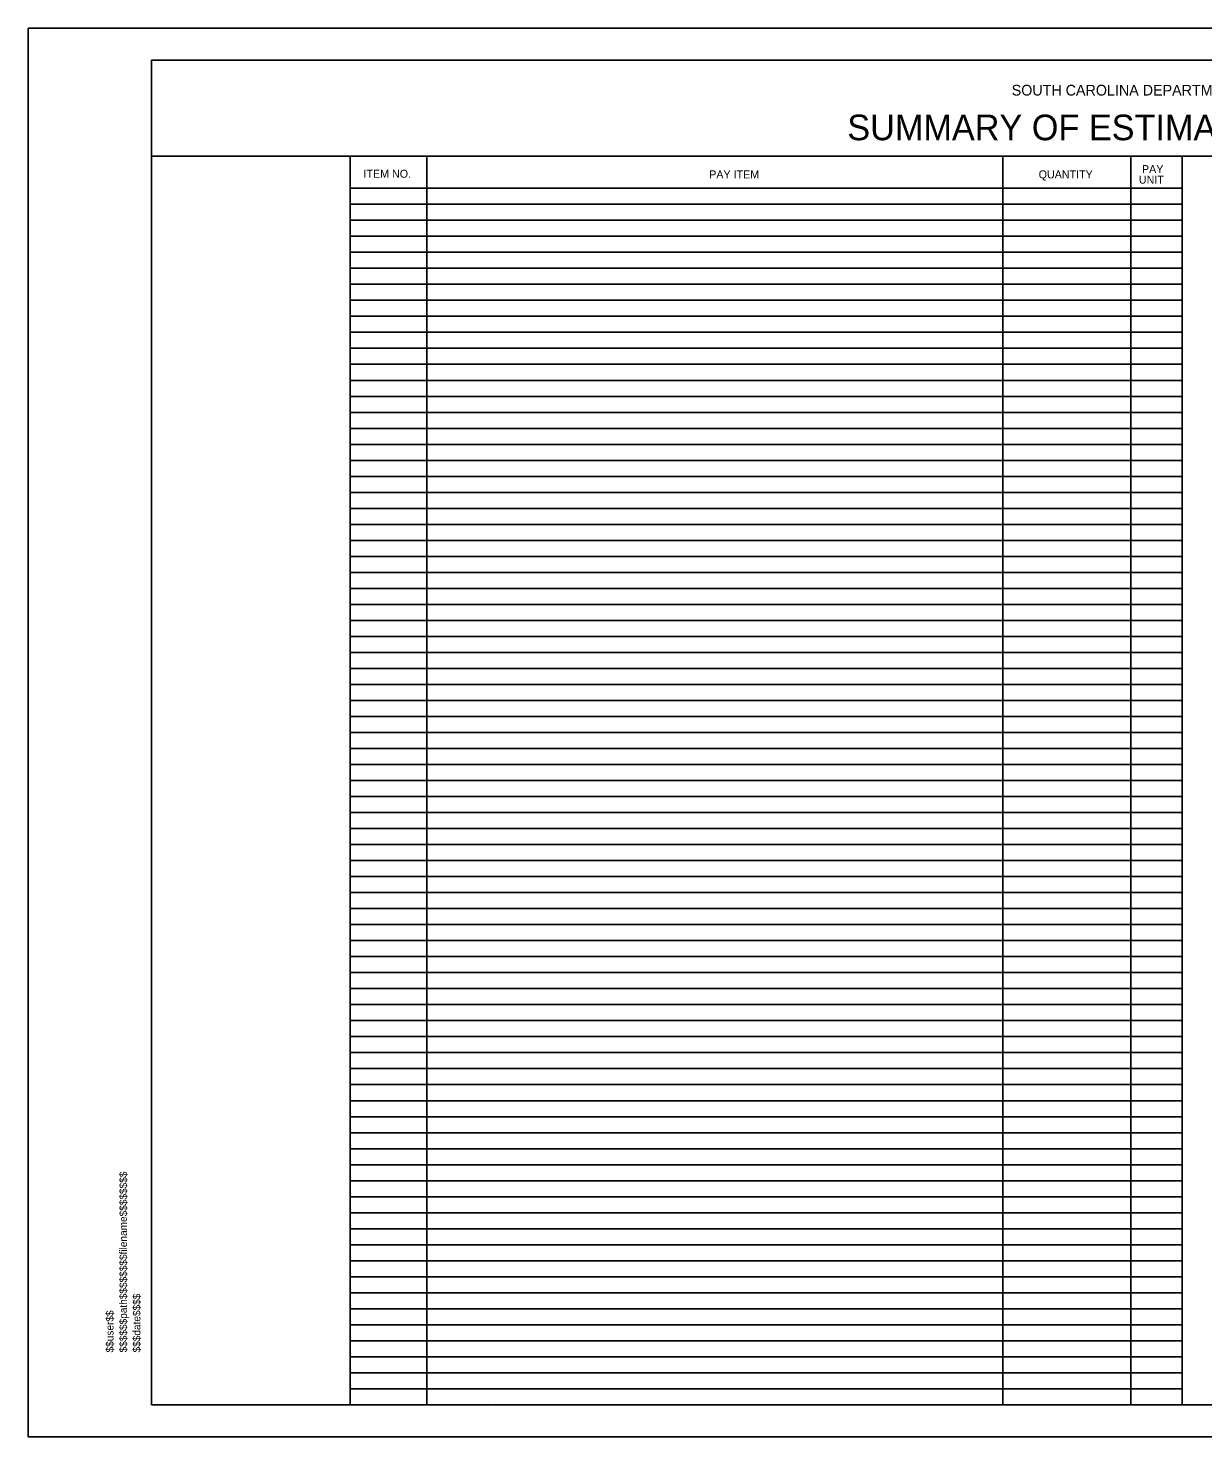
# Model space of a CAD drawing. Extents: x -796 to 2793, y -4650 to 4425.
# Drawn here: x 981 to 1899, y -1250 to -150 of the extents above; entities that cross this region are included whole.
import ezdxf

# ---------------------------------------------------------------- set-up
doc = ezdxf.new("R2010")
doc.units = 0
for name, color, linetype in [('RD_HC_CL', 7, 'Continuous'), ('RD_HC_Data', 7, 'Continuous'), ('RD_HC_Data_Tic', 7, 'Continuous'), ('RD_TX_Misc1', 7, 'Continuous')]:
    doc.layers.add(name, color=color, linetype=linetype)

msp = doc.modelspace()

# ---------------------------------------------------------------- linework, layer by layer
at = {"layer": 'RD_HC_CL'}
msp.add_lwpolyline([(981.4, -150), (2777.4, -150), (2777.4, -1250), (981.4, -1250)], close=True, dxfattribs=at)
at = {"layer": 'RD_HC_Data'}
for p, q in [((2760, -150), (1000, -150)), ((2760, -150), (1000, -150)), ((1077.8, -250), (1883, -250)), ((1233, -250), (1233, -1225)), ((1293, -250), (1293, -1225)), ((1627.8, -250), (2752.8, -250)), ((1743, -250), (1743, -1225)), ((1843, -250), (1843, -1225)), ((1883, -250), (1883, -1225)), ((1233, -275), (1883, -275)), ((1233, -287.5), (1883, -287.5)), ((1233, -300), (1883, -300)), ((1233, -312.5), (1883, -312.5)), ((1233, -325), (1883, -325)), ((1233, -337.5), (1883, -337.5)), ((1233, -350), (1883, -350)), ((1233, -362.5), (1883, -362.5)), ((1233, -375), (1883, -375)), ((1233, -387.5), (1883, -387.5)), ((1233, -400), (1883, -400)), ((1233, -412.5), (1883, -412.5)), ((1233, -425), (1883, -425)), ((1233, -437.5), (1883, -437.5)), ((1233, -450), (1883, -450)), ((1233, -462.5), (1883, -462.5)), ((1233, -475), (1883, -475)), ((1233, -487.5), (1883, -487.5)), ((1233, -500), (1883, -500)), ((1233, -512.5), (1883, -512.5)), ((1233, -525), (1883, -525)), ((1233, -537.5), (1883, -537.5)), ((1233, -550), (1883, -550)), ((1233, -562.5), (1883, -562.5)), ((1233, -575), (1883, -575)), ((1233, -587.5), (1883, -587.5)), ((1233, -600), (1883, -600)), ((1233, -612.5), (1883, -612.5)), ((1233, -625), (1883, -625)), ((1233, -637.5), (1883, -637.5)), ((1233, -650), (1883, -650)), ((1233, -662.5), (1883, -662.5)), ((1233, -675), (1883, -675)), ((1233, -687.5), (1883, -687.5)), ((1233, -700), (1883, -700)), ((1233, -712.5), (1883, -712.5)), ((1233, -725), (1883, -725)), ((1233, -737.5), (1883, -737.5)), ((1233, -750), (1883, -750)), ((1233, -762.5), (1883, -762.5)), ((1233, -775), (1883, -775)), ((1233, -787.5), (1883, -787.5)), ((1233, -800), (1883, -800)), ((1233, -812.5), (1883, -812.5)), ((1233, -825), (1883, -825)), ((1233, -837.5), (1883, -837.5)), ((1233, -850), (1883, -850)), ((1233, -862.5), (1883, -862.5)), ((1233, -875), (1883, -875)), ((1233, -887.5), (1883, -887.5)), ((1233, -900), (1883, -900)), ((1233, -912.5), (1883, -912.5)), ((1233, -925), (1883, -925)), ((1233, -937.5), (1883, -937.5)), ((1233, -950), (1883, -950)), ((1233, -962.5), (1883, -962.5)), ((1233, -974.9), (1883, -974.9)), ((1233, -987.5), (1883, -987.5)), ((1233, -1000), (1883, -1000)), ((1233, -1012.5), (1883, -1012.5)), ((1233, -1025), (1883, -1025)), ((1233, -1037.5), (1883, -1037.5)), ((1233, -1050), (1883, -1050)), ((1233, -1062.5), (1883, -1062.5)), ((1233, -1075), (1883, -1075)), ((1233, -1087.5), (1883, -1087.5)), ((1233, -1100), (1883, -1100)), ((1233, -1112.5), (1883, -1112.5)), ((1233, -1125), (1883, -1125)), ((1233, -1137.5), (1883, -1137.5)), ((1233, -1150), (1883, -1150)), ((1233, -1162.5), (1883, -1162.5)), ((1233, -1175), (1883.1, -1175)), ((1233, -1187.5), (1883, -1187.5)), ((1233, -1200), (1883, -1200)), ((1233, -1212.5), (1883, -1212.5)), ((1341.1, -1223.4), (1341.1, -1223.4)), ((2760, -1250), (1000, -1250)), ((1000, -1250), (2760, -1250))]:
    msp.add_line(p, q, dxfattribs=at)
msp.add_lwpolyline([(1077.8, -175), (2752.8, -175), (2752.8, -1225), (1077.8, -1225)], close=True, dxfattribs=at)

# ---------------------------------------------------------------- texts
at = {"layer": 'RD_HC_Data_Tic'}
for s, height, p in [('SOUTH CAROLINA DEPARTMENT OF TRANSPORTATION', 8.35, (1749.8, -202.6)), ('SUMMARY OF ESTIMATED QUANTITIES ', 20, (1621.4, -237.5)), ('ITEM NO.', 6.25, (1243.4, -266.8)), ('PAY ITEM', 6.25, (1513.5, -267.3)), ('QUANTITY', 6.25, (1770.9, -267.3)), ('PAY', 6.25, (1851.6, -263.2)), ('UNIT', 6.25, (1849.2, -271.4))]:
    msp.add_text(s, height=height, dxfattribs=at).set_placement(p)
at = {"layer": 'RD_TX_Misc1'}
for s, p in [('$$$$$$path$$$$$$$$filename$$$$$$$$', (1058.6, -1184.1)), ('$$$date$$$$', (1069.1, -1184.1)), ('$$user$$', (1048.1, -1184.1))]:
    msp.add_text(s, height=5.88, rotation=90, dxfattribs=at).set_placement(p)

doc.saveas('drawing.dxf')
